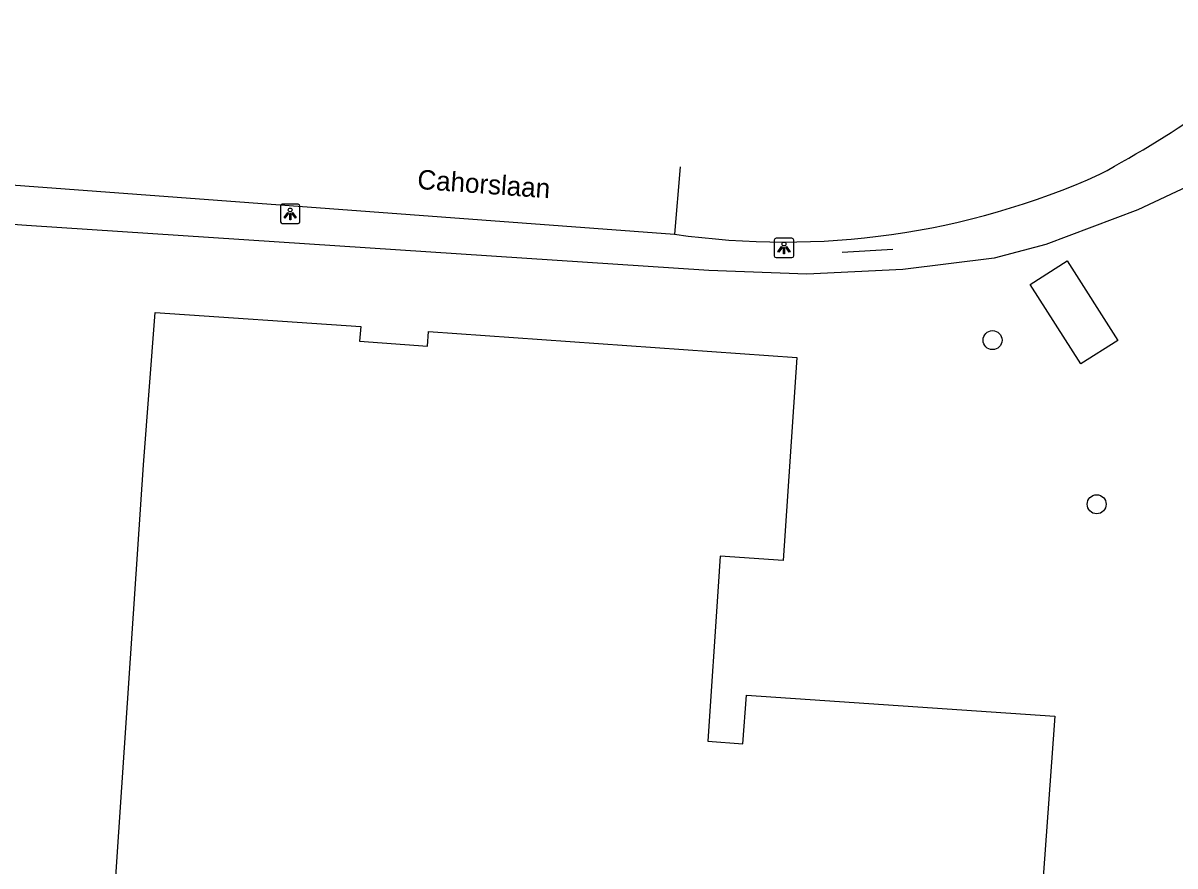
# Model space of a CAD drawing. Extents: x 158461 to 159795, y 387220 to 388672.
# Drawn here: x 158878.8 to 158938.1, y 388032.1 to 388075.5 of the extents above; entities that cross this region are included whole.
import ezdxf

# ---------------------------------------------------------------- set-up
doc = ezdxf.new("R2010")
doc.units = 0
for name, color, linetype in [('IMGEO_Boom', 7, 'Continuous'), ('IMGEO_Fietspad_gesloten', 7, 'Continuous'), ('IMGEO_Hek', 7, 'Continuous'), ('IMGEO_Lichtpunt', 7, 'Continuous'), ('IMGEO_Openbare_ruimte_label', 7, 'Continuous'), ('IMGEO_Pand', 7, 'Continuous'), ('IMGEO_Voetpad_open', 7, 'Continuous')]:
    doc.layers.add(name, color=color, linetype=linetype)

msp = doc.modelspace()

# ---------------------------------------------------------------- linework, layer by layer
at = {"layer": 'IMGEO_Boom'}
for centre in [(158928.69, 388059.194), (158934.044, 388050.748)]:
    msp.add_circle(centre, 0.489, dxfattribs=at)
at = {"layer": 'IMGEO_Fietspad_gesloten'}
for points in [[(158833.518, 388070.519), (158912.339, 388064.642)], [(158912.617, 388068.11), (158912.339, 388064.642)]]:
    msp.add_lwpolyline(points, dxfattribs=at)
for centre, radius, start, end in [((158906.121, 388119.617), 59.006, 298.42964, 311.62708), ((158917.967, 388103.83), 39.59, 261.82776, 294.22777)]:
    msp.add_arc(centre, radius, start, end, dxfattribs=at)
at = {"layer": 'IMGEO_Hek'}
msp.add_lwpolyline([(158923.554, 388063.855), (158920.957, 388063.699)], dxfattribs=at)
at = {"layer": 'IMGEO_Lichtpunt'}
for p, q in [((158892.072, 388066.095), (158892.072, 388065.288)), ((158892.072, 388066.095), (158892.072, 388065.288)), ((158892.974, 388066.19), (158892.166, 388066.19)), ((158892.974, 388066.19), (158892.166, 388066.19)), ((158893.068, 388065.288), (158893.068, 388066.095)), ((158893.068, 388065.288), (158893.068, 388066.095)), ((158892.166, 388065.194), (158892.974, 388065.194)), ((158892.166, 388065.194), (158892.974, 388065.194)), ((158917.467, 388064.344), (158917.467, 388063.537)), ((158917.467, 388064.344), (158917.467, 388063.537)), ((158918.369, 388064.439), (158917.561, 388064.439)), ((158918.369, 388064.439), (158917.561, 388064.439)), ((158918.463, 388063.537), (158918.463, 388064.344)), ((158918.463, 388063.537), (158918.463, 388064.344)), ((158917.561, 388063.443), (158918.369, 388063.443)), ((158917.561, 388063.443), (158918.369, 388063.443))]:
    msp.add_line(p, q, dxfattribs=at)
for points in [[(158892.446, 388065.759), (158892.485, 388065.731), (158892.297, 388065.469), (158892.259, 388065.496), (158892.446, 388065.759)], [(158892.548, 388065.711), (158892.595, 388065.711), (158892.595, 388065.389), (158892.548, 388065.389), (158892.548, 388065.711)], [(158892.658, 388065.731), (158892.696, 388065.758), (158892.883, 388065.496), (158892.844, 388065.468), (158892.658, 388065.731)], [(158917.841, 388064.008), (158917.88, 388063.98), (158917.692, 388063.718), (158917.654, 388063.745), (158917.841, 388064.008)], [(158917.943, 388063.96), (158917.99, 388063.96), (158917.99, 388063.638), (158917.943, 388063.638), (158917.943, 388063.96)], [(158918.053, 388063.98), (158918.091, 388064.007), (158918.278, 388063.745), (158918.239, 388063.717), (158918.053, 388063.98)]]:
    msp.add_lwpolyline(points, dxfattribs=at)
for centre in [(158892.571, 388065.893), (158917.966, 388064.142)]:
    msp.add_circle(centre, 0.0994, dxfattribs=at)
for centre, start, end in [((158892.166, 388066.095), 90, 180), ((158892.166, 388066.095), 90, 180), ((158892.974, 388066.095), 0, 90), ((158892.974, 388066.095), 0, 90), ((158892.166, 388065.288), 180, 270), ((158892.166, 388065.288), 180, 270), ((158892.974, 388065.288), 270, 0), ((158892.974, 388065.288), 270, 360), ((158917.561, 388064.344), 90, 180), ((158917.561, 388064.344), 90, 180), ((158918.369, 388064.344), 0, 90), ((158918.369, 388064.344), 0, 90), ((158917.561, 388063.537), 180, 270), ((158917.561, 388063.537), 180, 270), ((158918.369, 388063.537), 270, 0), ((158918.369, 388063.537), 270, 360)]:
    msp.add_arc(centre, 0.0946, start, end, dxfattribs=at)
at = {"layer": 'IMGEO_Pand'}
for points in [[(158933.238, 388057.97), (158930.624, 388062.062), (158932.52, 388063.273), (158935.134, 388059.181), (158933.238, 388057.97)], [(158883.531, 388030.561), (158885.031, 388052.783), (158885.633, 388060.609), (158896.203, 388059.893), (158896.137, 388059.147), (158899.627, 388058.884), (158899.684, 388059.632), (158918.627, 388058.298), (158917.917, 388047.863), (158914.687, 388048.082), (158914.581, 388046.513), (158914.041, 388038.556), (158915.847, 388038.422), (158916.032, 388040.926), (158931.886, 388039.84), (158930.747, 388023.981)]]:
    msp.add_lwpolyline(points, dxfattribs=at)
at = {"layer": 'IMGEO_Voetpad_open'}
msp.add_lwpolyline([(158953.249, 388074.447), (158952.754, 388075.22), (158941.791, 388068.535), (158936.153, 388065.891), (158931.434, 388064.116), (158928.765, 388063.418), (158924.075, 388062.823), (158919.147, 388062.587), (158914.099, 388062.781), (158879.005, 388065.098), (158858.983, 388066.573)], dxfattribs=at)

# ---------------------------------------------------------------- texts
at = {"layer": 'IMGEO_Openbare_ruimte_label'}
msp.add_text('Cahorslaan', height=1, rotation=355.92664, dxfattribs=at).set_placement((158899.084, 388066.977))

doc.saveas('drawing.dxf')
